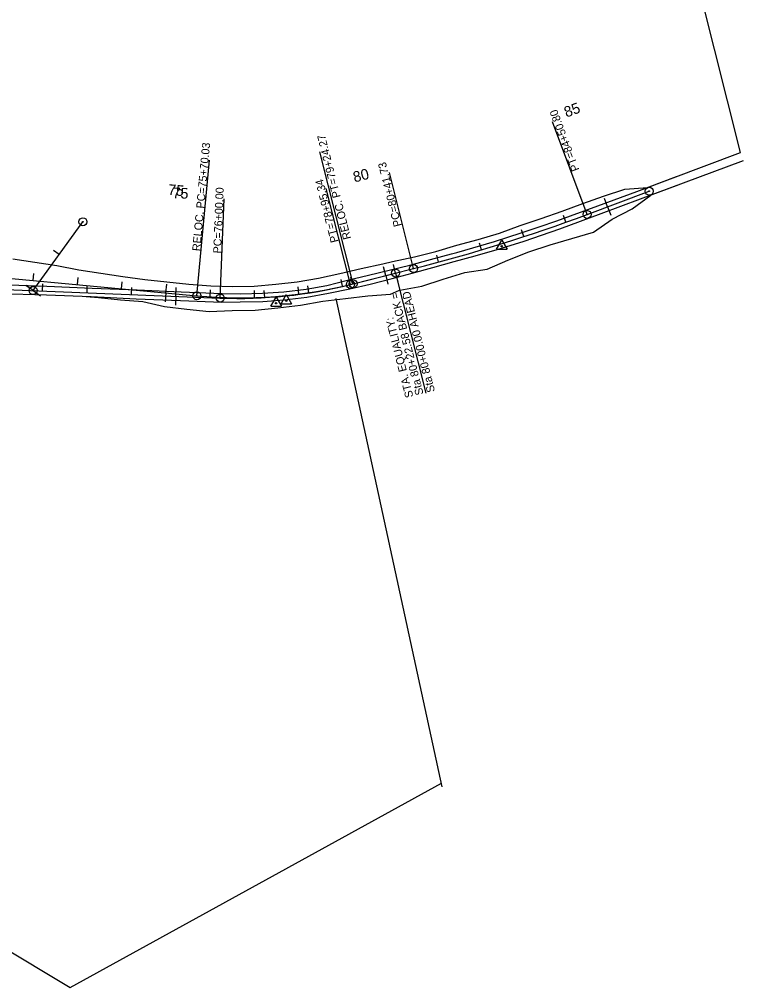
# Model space of a CAD drawing. Extents: x 1965308 to 1970456, y 1116335 to 1119906.
# Drawn here: x 1968827 to 1970456, y 1116335 to 1118511 of the extents above; entities that cross this region are included whole.
import ezdxf

# ---------------------------------------------------------------- set-up
doc = ezdxf.new("R2010")
doc.units = 0
for name, color, linetype in [('RD_EX_DV_Prop', 7, 'Continuous'), ('RD_EX_Road', 7, 'Continuous'), ('RD_EX_RW', 7, 'Continuous'), ('RD_HC_Cl', 7, 'Continuous'), ('RD_HC_CL_Rel', 7, 'Continuous'), ('RD_HC_Data', 7, 'Continuous'), ('RD_HC_Data_Rel', 7, 'Continuous'), ('RD_HC_Data_Tic', 7, 'Continuous'), ('RD_HC_Data_Tic_Rel', 7, 'Continuous'), ('RD_HC_TX_Rel_Sta50', 7, 'Continuous'), ('RD_HC_TX_StaOther', 7, 'Continuous'), ('RD_PD_RW', 7, 'Continuous'), ('RD_SMD_Locator', 7, 'Continuous')]:
    doc.layers.add(name, color=color, linetype=linetype)

msp = doc.modelspace()

# ---------------------------------------------------------------- linework, layer by layer
at = {"layer": 'RD_EX_DV_Prop'}
for p, q in [((1970449.4, 1118212.4), (1970021.7, 1119906.4)), ((1969538.9, 1117883.9), (1969777.4, 1116786.4)), ((1968941.8, 1116334.8), (1969776.6, 1116794.1)), ((1968719.5, 1116468.1), (1968941.8, 1116334.8))]:
    msp.add_line(p, q, dxfattribs=at)
at = {"layer": 'RD_EX_Road'}
for points in [[(1969956, 1118031.2), (1969996, 1118044.6), (1970036.1, 1118058.4), (1970128.5, 1118091.9), (1970215.9, 1118124.3), (1970305.1, 1118158)], [(1969962.3, 1118013), (1970001.8, 1118026.3), (1970042.5, 1118040.4), (1970135.4, 1118074.7), (1970224, 1118107.7), (1970311.2, 1118140.2)], [(1969810.8, 1117987.5), (1969847, 1117997.6), (1969895.7, 1118011.9), (1969956, 1118031.2)], [(1969282.9, 1117875.4), (1969323.9, 1117876.1), (1969374.9, 1117877.1), (1969422.8, 1117880.6), (1969473.4, 1117886.6), (1969522.6, 1117895.5), (1969570.2, 1117905.2), (1969616.1, 1117916.1), (1969665.8, 1117928.6), (1969710.9, 1117940.6), (1969757.1, 1117953.2), (1969805.3, 1117966.7), (1969852.3, 1117979.8), (1969901.9, 1117994.1), (1969962.3, 1118013)], [(1969283.3, 1117895.4), (1969325.6, 1117894.4), (1969373.8, 1117895.6), (1969422.2, 1117898.6), (1969472.1, 1117904.7), (1969518.5, 1117913.1), (1969565.2, 1117925.2), (1969612.4, 1117936.1), (1969659.1, 1117947.3), (1969705.6, 1117959), (1969751.6, 1117971.4), (1969799.2, 1117984.2), (1969810.8, 1117987.5)], [(1968530.5, 1117925.7), (1968682, 1117919), (1968783.2, 1117915.4), (1968888.6, 1117911.4), (1968991.2, 1117907.1), (1969092, 1117903.1), (1969191.1, 1117898.7), (1969283.3, 1117895.4)], [(1968527.8, 1117906.4), (1968680.8, 1117899.1), (1968781.7, 1117895.4), (1968887.9, 1117891.8), (1968988.7, 1117888.2), (1969090.1, 1117882.8), (1969189.3, 1117879), (1969282.9, 1117875.4)]]:
    msp.add_lwpolyline(points, dxfattribs=at)
at = {"layer": 'RD_EX_RW'}
for points in [[(1969956, 1118031.2), (1969996, 1118044.6), (1970036.1, 1118058.4), (1970128.5, 1118091.9), (1970215.9, 1118124.3), (1970449.4, 1118212.4)], [(1969962.3, 1118013), (1970001.8, 1118026.3), (1970042.5, 1118040.4), (1970135.4, 1118074.7), (1970224, 1118107.7), (1970456.1, 1118194.3)], [(1969810.8, 1117987.5), (1969847, 1117997.6), (1969895.7, 1118011.9), (1969956, 1118031.2)], [(1969282.9, 1117875.4), (1969323.9, 1117876.1), (1969374.9, 1117877.1), (1969422.8, 1117880.6), (1969473.4, 1117886.6), (1969522.6, 1117895.5), (1969570.2, 1117905.2), (1969616.1, 1117916.1), (1969665.8, 1117928.6), (1969710.9, 1117940.6), (1969757.1, 1117953.2), (1969805.3, 1117966.7), (1969852.3, 1117979.8), (1969901.9, 1117994.1), (1969962.3, 1118013)], [(1969283.3, 1117895.4), (1969325.6, 1117894.4), (1969373.8, 1117895.6), (1969422.2, 1117898.6), (1969472.1, 1117904.7), (1969518.5, 1117913.1), (1969565.2, 1117925.2), (1969612.4, 1117936.1), (1969659.1, 1117947.3), (1969705.6, 1117959), (1969751.6, 1117971.4), (1969799.2, 1117984.2), (1969810.8, 1117987.5)], [(1968530.5, 1117925.7), (1968682, 1117919), (1968783.2, 1117915.4), (1968888.6, 1117911.4), (1968991.2, 1117907.1), (1969092, 1117903.1), (1969191.1, 1117898.7), (1969283.3, 1117895.4)], [(1968527.8, 1117906.4), (1968680.8, 1117899.1), (1968781.7, 1117895.4), (1968887.9, 1117891.8), (1968988.7, 1117888.2), (1969090.1, 1117882.8), (1969189.3, 1117879), (1969282.9, 1117875.4)]]:
    msp.add_lwpolyline(points, dxfattribs=at)
at = {"layer": 'RD_HC_Cl'}
for p, q in [((1970104, 1118072.9), (1970243.8, 1118125.1)), ((1968858.2, 1117901.7), (1968970.1, 1118056.2)), ((1969571.8, 1117915.4), (1969713.7, 1117951.2)), ((1968120.3, 1117930.9), (1969279, 1117884.9))]:
    msp.add_line(p, q, dxfattribs=at)
for centre, radius, start, end in [((1968809, 1121539.8), 3700.9, 284.1493, 290.4823), ((1969319.9, 1118914.5), 1030.4, 267.7266, 284.1493)]:
    msp.add_arc(centre, radius, start, end, dxfattribs=at)
at = {"layer": 'RD_HC_CL_Rel'}
for p, q in [((1968277.4, 1117978.5), (1969226.4, 1117889.9)), ((1969577.9, 1117916.9), (1969673.3, 1117941))]:
    msp.add_line(p, q, dxfattribs=at)
msp.add_arc((1969323.3, 1118927.1), 1041.7, 264.6661, 284.1493, dxfattribs=at)
at = {"layer": 'RD_HC_Data'}
for p, q in [((1970104, 1118072.9), (1970026.3, 1118280.9)), ((1969713.7, 1117951.2), (1969659.4, 1118166.7)), ((1969571.8, 1117915.4), (1969517.5, 1118130.8)), ((1969279, 1117884.9), (1969287.9, 1118108.1)), ((1969900.3, 1117994.4), (1969912.2, 1118015)), ((1969912.2, 1118015), (1969924.2, 1117994.4)), ((1969900.3, 1117994.4), (1969924.2, 1117994.4)), ((1969415.7, 1117872.2), (1969427.6, 1117892.8)), ((1969427.6, 1117892.8), (1969439.5, 1117872.2)), ((1969415.7, 1117872.2), (1969439.5, 1117872.2))]:
    msp.add_line(p, q, dxfattribs=at)
for centre, radius in [((1970243.8, 1118125.1), 9), ((1970243.8, 1118125.1), 0.845), ((1970104, 1118072.9), 9), ((1970104, 1118072.9), 0.845), ((1968970.1, 1118056.2), 9), ((1968970.1, 1118056.2), 0.845), ((1969912.2, 1118001.2), 1.59), ((1969713.7, 1117951.2), 9), ((1969713.7, 1117951.2), 0.845), ((1969571.8, 1117915.4), 9), ((1968858.2, 1117901.7), 9), ((1968858.2, 1117901.7), 0.845), ((1969571.8, 1117915.4), 0.845), ((1969279, 1117884.9), 9), ((1969279, 1117884.9), 9), ((1969279, 1117884.9), 0.845), ((1969279, 1117884.9), 0.845), ((1969427.6, 1117879), 1.59)]:
    msp.add_circle(centre, radius, dxfattribs=at)
at = {"layer": 'RD_HC_Data_Rel'}
for p, q in [((1969577.9, 1117916.9), (1969503.2, 1118213.2)), ((1969226.4, 1117889.9), (1969254.9, 1118194.5)), ((1969673.3, 1117941), (1969741.3, 1117671.2)), ((1969392.6, 1117866.4), (1969404.5, 1117887)), ((1969404.5, 1117887), (1969416.4, 1117866.4)), ((1969392.6, 1117866.4), (1969416.4, 1117866.4))]:
    msp.add_line(p, q, dxfattribs=at)
for centre, radius in [((1969673.3, 1117941), 9), ((1969673.3, 1117941), 0.845), ((1969577.9, 1117916.9), 9), ((1969226.4, 1117889.9), 9), ((1969577.9, 1117916.9), 0.845), ((1969226.4, 1117889.9), 0.845), ((1969404.5, 1117873.2), 1.59)]:
    msp.add_circle(centre, radius, dxfattribs=at)
at = {"layer": 'RD_HC_Data_Tic'}
for p, q in [((1970150.1, 1118090.1), (1970143.1, 1118108.8)), ((1970150.1, 1118090.1), (1970157.1, 1118071.4)), ((1970056.3, 1118055.4), (1970050.9, 1118070.5)), ((1969961.7, 1118023), (1969956.8, 1118038.2)), ((1969866.3, 1117993.1), (1969861.7, 1118008.5)), ((1968916.8, 1117982.6), (1968903.9, 1117992)), ((1969770.1, 1117965.9), (1969765.9, 1117981.3)), ((1969673.3, 1117941), (1969668.4, 1117960.4)), ((1969576.3, 1117916.5), (1969572.4, 1117932)), ((1969673.3, 1117941), (1969678.1, 1117921.6)), ((1968858.2, 1117901.7), (1968842, 1117913.4)), ((1968858.2, 1117901.7), (1968874.4, 1117889.9)), ((1968879.3, 1117900.8), (1968880, 1117916.8)), ((1968979.3, 1117896.8), (1968979.9, 1117912.8)), ((1969079.2, 1117892.9), (1969079.8, 1117908.9)), ((1969179.1, 1117888.9), (1969179.9, 1117908.9)), ((1969279, 1117884.9), (1969279.7, 1117900.9)), ((1969379, 1117885.8), (1969378.1, 1117901.8)), ((1969478.4, 1117896.4), (1969475.9, 1117912.2)), ((1969179.1, 1117888.9), (1969178.3, 1117868.9))]:
    msp.add_line(p, q, dxfattribs=at)
at = {"layer": 'RD_HC_Data_Tic_Rel'}
for p, q in [((1969651.4, 1117935.5), (1969646.5, 1117954.9)), ((1969673.3, 1117941), (1969668.4, 1117960.4)), ((1968858, 1117924.3), (1968859.5, 1117940.2)), ((1968957.6, 1117915), (1968959.1, 1117930.9)), ((1969057.1, 1117905.7), (1969058.6, 1117921.6)), ((1969554.3, 1117911.3), (1969550.8, 1117926.9)), ((1969651.4, 1117935.5), (1969656.2, 1117916.1)), ((1969673.3, 1117941), (1969678.1, 1117921.6)), ((1969156.7, 1117896.4), (1969158.6, 1117916.3)), ((1969256.3, 1117887.5), (1969257.3, 1117903.5)), ((1969356.3, 1117885.9), (1969355.7, 1117901.9)), ((1969455.9, 1117893.8), (1969453.9, 1117909.7)), ((1969156.7, 1117896.4), (1969154.8, 1117876.5))]:
    msp.add_line(p, q, dxfattribs=at)
at = {"layer": 'RD_PD_RW'}
for p, q in [((1970141.3, 1118113.7), (1970189, 1118129.4)), ((1970189, 1118129.4), (1970240.6, 1118133.6)), ((1970205.4, 1118085.5), (1970247.1, 1118116.3)), ((1970047.6, 1118079.9), (1970094.1, 1118097.2)), ((1970094.1, 1118097.2), (1970141.3, 1118113.7)), ((1970000.7, 1118063.7), (1970047.6, 1118079.9)), ((1970160.7, 1118062.2), (1970205.4, 1118085.5)), ((1969953.5, 1118048.1), (1970000.7, 1118063.7)), ((1970118.2, 1118033), (1970160.7, 1118062.2)), ((1969859.3, 1118016.8), (1969906.9, 1118030.7)), ((1969906.9, 1118030.7), (1969953.5, 1118048.1)), ((1970069.5, 1118018.4), (1970118.2, 1118033)), ((1969811.3, 1118003.8), (1969859.3, 1118016.8)), ((1970021, 1118004.3), (1970069.5, 1118018.4)), ((1969715.5, 1117977.8), (1969763.8, 1117989.5)), ((1969763.8, 1117989.5), (1969811.3, 1118003.8)), ((1969926.1, 1117969.8), (1969973, 1117988.8)), ((1969973, 1117988.8), (1970021, 1118004.3)), ((1968812.3, 1117973.2), (1968861.9, 1117965.3)), ((1968861.9, 1117965.3), (1968911.5, 1117958.1)), ((1969644.7, 1117962.1), (1969666.2, 1117966.9)), ((1969666.2, 1117966.9), (1969666.7, 1117967)), ((1969666.7, 1117967), (1969715.5, 1117977.8)), ((1969879.2, 1117950), (1969926.1, 1117969.8)), ((1968911.5, 1117958.1), (1968960.8, 1117948.4)), ((1968960.8, 1117948.4), (1969010.3, 1117940.7)), ((1969547.8, 1117940), (1969595.8, 1117951.3)), ((1969595.8, 1117951.3), (1969644.7, 1117962.1)), ((1969780.5, 1117927.3), (1969828.7, 1117942.3)), ((1969828.7, 1117942.3), (1969879.2, 1117950)), ((1969010.3, 1117940.7), (1969059.7, 1117933)), ((1969059.7, 1117933), (1969109.4, 1117926.8)), ((1969109.4, 1117926.8), (1969159, 1117921.2)), ((1969159, 1117921.2), (1969208.7, 1117915.7)), ((1969404, 1117915.8), (1969452.3, 1117921.4)), ((1969452.3, 1117921.4), (1969500.2, 1117929.9)), ((1969500.2, 1117929.9), (1969547.8, 1117940)), ((1969732.3, 1117911.7), (1969780.5, 1117927.3)), ((1969208.7, 1117915.7), (1969257.9, 1117912.1)), ((1969257.9, 1117912.1), (1969306.7, 1117911)), ((1969306.7, 1117911), (1969355.4, 1117911.9)), ((1969355.4, 1117911.9), (1969404, 1117915.8)), ((1969662, 1117893.3), (1969682.4, 1117902.4)), ((1969682.4, 1117902.4), (1969682.9, 1117902.5)), ((1969682.9, 1117902.5), (1969732.3, 1117911.7)), ((1968977.1, 1117888.6), (1969005.1, 1117886)), ((1969005.1, 1117886), (1969054.8, 1117881.1)), ((1969054.8, 1117881.1), (1969104.6, 1117876.8)), ((1969104.6, 1117876.8), (1969153.8, 1117866.1)), ((1969459.1, 1117868.8), (1969509.5, 1117877.5)), ((1969509.5, 1117877.5), (1969560.4, 1117884.1)), ((1969560.4, 1117884.1), (1969611.2, 1117889.6)), ((1969611.2, 1117889.6), (1969662, 1117893.3)), ((1969153.8, 1117866.1), (1969203.5, 1117860.1)), ((1969203.5, 1117860.1), (1969254.2, 1117854.5)), ((1969254.2, 1117854.5), (1969305.8, 1117856.9)), ((1969305.8, 1117856.9), (1969357.2, 1117857.5)), ((1969357.2, 1117857.5), (1969408.3, 1117862.5)), ((1969408.3, 1117862.5), (1969459.1, 1117868.8))]:
    msp.add_line(p, q, dxfattribs=at)
at = {"layer": 'RD_SMD_Locator'}
for centre in [(1970243.8, 1118125.1), (1970104, 1118072.9), (1968970.1, 1118056.2), (1969912.2, 1118001.2), (1969713.7, 1117951.2), (1968858.2, 1117901.7), (1969571.8, 1117915.4), (1969279, 1117884.9), (1969279, 1117884.9), (1969427.6, 1117879)]:
    msp.add_circle(centre, 0.003, dxfattribs=at)

# ---------------------------------------------------------------- texts
at = {"layer": 'RD_HC_Data'}
for s, rotation, p in [('PT=84+50.80', 110.4823, (1970087.1, 1118173.6)), ('PC=80+41.73', 104.1493, (1969687.3, 1118047.7)), ('PT=78+95.34', 104.1493, (1969545.4, 1118011.9)), ('PC=76+00.00', 87.7266, (1969281, 1117984.9))]:
    msp.add_text(s, height=18, rotation=rotation, dxfattribs=at).set_placement(p)
at = {"layer": 'RD_HC_Data_Rel'}
for s, rotation, p in [('RELOC. PT=79+24.27', 104.1493, (1969573.4, 1118018.9)), ('RELOC. PC=75+70.03', 84.6661, (1969233.7, 1117989.6)), ('Sta 80+00.00 AHEAD', 104.1493, (1969762.1, 1117675.2)), ('Sta 80+22.58 BACK = ', 104.1493, (1969736.4, 1117668.9)), ('STA. EQUALITY:', 104.1493, (1969713.4, 1117663.1))]:
    msp.add_text(s, height=18, rotation=rotation, dxfattribs=at).set_placement(p)
at = {"layer": 'RD_HC_TX_Rel_Sta50'}
for s, rotation, p in [('80', 14.1493, (1969581, 1118144.6)), ('75', 354.6661, (1969160.7, 1118117))]:
    msp.add_text(s, height=24, rotation=rotation, dxfattribs=at).set_placement(p)
at = {"layer": 'RD_HC_TX_StaOther'}
for s, rotation, p in [('85', 20.4823, (1970057.6, 1118290.4)), ('75', 357.7266, (1969171.3, 1118109.4))]:
    msp.add_text(s, height=24, rotation=rotation, dxfattribs=at).set_placement(p)

doc.saveas('drawing.dxf')
